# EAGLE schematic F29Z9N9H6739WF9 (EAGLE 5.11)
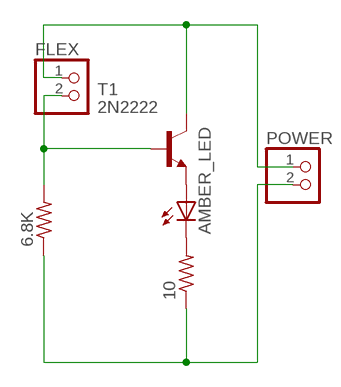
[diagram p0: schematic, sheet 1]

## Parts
6.8K  R-US_0207/10  [0207/10]
10  R-US_0207/10  [0207/10]
AMBER_LED  LED5MM  [LED5MM]
FLEX  PINHD-1X2  [1X02]
POWER  PINHD-1X2  [1X02]
T1  2N2222  [TO92-EBC-OVAL]

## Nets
N$1: FLEX.1 POWER.1 T1.C
N$2: AMBER_LED.A T1.E
N$3: 10.2 AMBER_LED.K(C)
N$4: 6.8K.1 10.1 POWER.2
N$5: 6.8K.2 FLEX.2 T1.B

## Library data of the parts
6.8K 10 = adafruit:R-US_: RESISTOR, American symbol
AMBER_LED = adafruit:LED: LED
FLEX POWER = pinhead:PINHD-1X2: PIN HEADER
T1 = adafruit:2N2222: NPN TRANSISTOR Big oval pads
